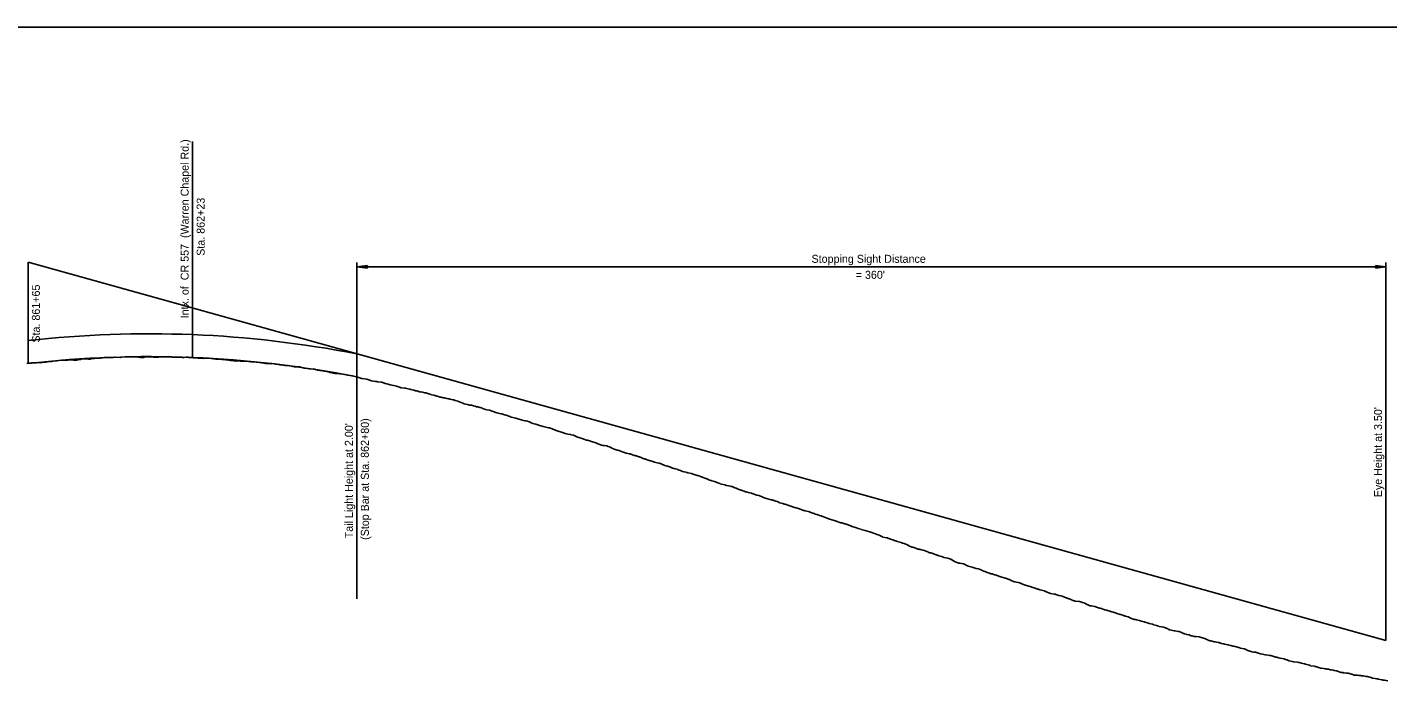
# Model space of a CAD drawing. Extents: x -1395 to 1843, y -1176 to 1887.
# Drawn here: x 1124.1 to 1600, y 762.7 to 991.4 of the extents above; entities that cross this region are included whole.
import ezdxf

# ---------------------------------------------------------------- set-up
doc = ezdxf.new("R2010")
doc.units = 0
doc.layers.add('SV_X_Toe_of_Slope', color=7, linetype='Continuous')
doc.layers.add('UT_X_Telecom', color=7, linetype='Continuous')

msp = doc.modelspace()

# ---------------------------------------------------------------- linework, layer by layer
at = {"layer": 'SV_X_Toe_of_Slope'}
for p, q in [((1059.41, 991.44), (1659.41, 991.44)), ((1181.98, 875.86), (1181.98, 951.44)), ((1124.41, 873.75), (1124.41, 909.2)), ((1124.41, 909.2), (1599.41, 776.77)), ((1239.41, 791.44), (1239.41, 909.13)), ((1599.41, 776.77), (1599.41, 909.13)), ((1239.41, 907.59), (1243.12, 908.08)), ((1239.41, 907.59), (1599.41, 907.59)), ((1243.11, 907.09), (1239.41, 907.59)), ((1243.11, 907.09), (1243.11, 907.09)), ((1243.12, 908.08), (1243.12, 908.08)), ((1599.41, 907.59), (1595.7, 907.09)), ((1595.7, 907.09), (1595.71, 907.09)), ((1595.72, 908.08), (1595.72, 908.08)), ((1595.72, 908.08), (1599.41, 907.59))]:
    msp.add_line(p, q, dxfattribs=at)
for centre, major_axis, ratio, start_param, end_param in [((1244.06, 907.58), (-1.13, 0), 0.8, 5.69288, 6.856679), ((1594.77, 907.6), (1.13, 0), 0.8, 5.69288, 6.856679), ((1166.87, -5112.73), (0, 5996.89), 0.25, 6.234777, 6.311506), ((1166.87, -5112.73), (0, 5988.89), 0.25, 6.234712, 6.311544)]:
    msp.add_ellipse(centre, major_axis=major_axis, ratio=ratio, start_param=start_param, end_param=end_param, dxfattribs=at)
at = {"layer": 'UT_X_Telecom'}
msp.add_lwpolyline([(1123.99, 873.76), (1125.65, 874.04), (1125.77, 874.04), (1127.25, 874.02), (1127.58, 874.08), (1128.53, 874.04), (1128.88, 874.05), (1129.16, 874.12), (1129.39, 874.16), (1130.64, 874.24), (1130.65, 874.24), (1130.66, 874.24), (1131.16, 874.36), (1132.5, 874.44), (1132.56, 874.44), (1132.64, 874.47), (1132.9, 874.57), (1133.13, 874.59), (1134.05, 874.66), (1134.46, 874.68), (1134.52, 874.71), (1135.02, 874.8), (1136.15, 874.87), (1136.2, 874.87), (1136.46, 874.94), (1137.1, 874.94), (1137.85, 874.93), (1137.9, 874.92), (1137.98, 874.94), (1138.36, 874.98), (1139.32, 875.02), (1139.54, 875.03), (1139.62, 875.03), (1140.2, 874.99), (1140.47, 874.97), (1141.15, 874.92), (1141.49, 874.98), (1142.4, 875.19), (1142.72, 875.21), (1142.93, 875.26), (1144.02, 875.44), (1144.18, 875.43), (1144.42, 875.37), (1145.51, 875.27), (1145.89, 875.25), (1146.07, 875.24), (1146.39, 875.35), (1147.52, 875.54), (1147.91, 875.58), (1149.1, 875.6), (1149.19, 875.6), (1149.57, 875.57), (1149.59, 875.58), (1150.49, 875.73), (1151.02, 875.83), (1151.21, 875.81), (1151.26, 875.8), (1151.27, 875.8), (1151.31, 875.8), (1152.9, 875.84), (1152.93, 875.84), (1153.68, 875.87), (1154.12, 875.88), (1154.69, 875.92), (1154.85, 875.92), (1156.61, 875.91), (1156.93, 875.99), (1158.2, 876.05), (1158.38, 876.04), (1158.49, 876.05), (1159.8, 876.08), (1160.01, 876.07), (1160.37, 876.1), (1160.46, 876.12), (1161.53, 876.08), (1161.55, 876.08), (1161.96, 876.12), (1162.01, 876.12), (1162.05, 876.11), (1163.08, 875.95), (1163.58, 875.9), (1163.75, 875.91), (1164.62, 875.9), (1164.76, 875.9), (1165.1, 875.99), (1165.39, 876.06), (1166.64, 876.11), (1166.68, 876.12), (1166.91, 876.09), (1168.25, 875.95), (1168.33, 875.93), (1168.42, 875.93), (1168.91, 875.95), (1169.49, 875.98), (1170.01, 876.02), (1170.79, 876.04), (1171.78, 876.07), (1172.24, 876.11), (1172.74, 876.14), (1173.4, 876.16), (1173.58, 876.14), (1174.13, 876.05), (1174.66, 876), (1175.25, 875.94), (1175.41, 875.92), (1176.44, 875.99), (1176.57, 876), (1176.6, 876), (1177.13, 876), (1178.34, 875.89), (1178.4, 875.89), (1178.45, 875.88), (1178.5, 875.89), (1178.9, 875.89), (1179.66, 875.94), (1180.29, 875.95), (1180.64, 875.88), (1181.26, 875.84), (1182.1, 875.79), (1182.38, 875.76), (1183.3, 875.71), (1183.92, 875.66), (1184.12, 875.63), (1184.94, 875.61), (1185.44, 875.58), (1185.75, 875.56), (1185.82, 875.57), (1187.45, 875.6), (1187.49, 875.6), (1187.5, 875.6), (1187.51, 875.6), (1187.62, 875.59), (1189.25, 875.42), (1190.09, 875.32), (1190.85, 875.24), (1190.94, 875.24), (1191.05, 875.23), (1192.23, 875.14), (1192.39, 875.12), (1192.65, 875.11), (1193.52, 875.04), (1193.86, 875), (1194.48, 874.98), (1194.78, 874.91), (1195.18, 874.83), (1195.4, 874.78), (1196.4, 874.71), (1196.75, 874.69), (1196.95, 874.62), (1197.93, 874.65), (1198.38, 874.66), (1198.7, 874.62), (1200.37, 874.61), (1200.48, 874.61), (1200.62, 874.6), (1200.65, 874.59), (1202.33, 874.31), (1202.51, 874.29), (1202.61, 874.29), (1202.66, 874.29), (1203.69, 874.3), (1204.17, 874.26), (1204.31, 874.24), (1204.51, 874.22), (1205.34, 874.11), (1205.94, 874.05), (1206.04, 874.03), (1206.22, 873.99), (1207.49, 873.8), (1207.73, 873.76), (1207.84, 873.77), (1208.79, 873.74), (1209.35, 873.68), (1209.67, 873.7), (1210.47, 873.63), (1210.94, 873.56), (1211.25, 873.54), (1211.58, 873.48), (1212.53, 873.34), (1212.6, 873.33), (1212.75, 873.3), (1213.5, 873.2), (1214.1, 873.12), (1214.29, 873.1), (1215.03, 873.07), (1215.36, 873.06), (1215.8, 872.97), (1216.01, 872.91), (1216.61, 872.81), (1217.52, 872.57), (1217.81, 872.56), (1219.35, 872.54), (1220.98, 872.16), (1221.01, 872.16), (1221.01, 872.16), (1221.19, 872.12), (1222.09, 871.97), (1222.84, 871.84), (1222.88, 871.84), (1222.97, 871.84), (1224.59, 871.8), (1224.66, 871.79), (1224.92, 871.7), (1225.79, 871.44), (1225.87, 871.41), (1226.06, 871.37), (1226.56, 871.27), (1227.35, 871.24), (1227.65, 871.24), (1227.8, 871.21), (1228.14, 871.13), (1229.34, 870.83), (1229.48, 870.81), (1230.12, 870.65), (1231.11, 870.34), (1231.28, 870.35), (1231.66, 870.3), (1232.54, 870.28), (1232.8, 870.27), (1233.42, 870.15), (1233.85, 870.11), (1233.97, 870.09), (1234.56, 870), (1235.15, 869.93), (1235.94, 869.79), (1236.27, 869.72), (1237.18, 869.56), (1237.86, 869.42), (1238.31, 869.32), (1239.34, 869.1), (1239.52, 869.03), (1239.65, 869.01), (1240.08, 868.84), (1241.03, 868.54), (1241.17, 868.52), (1241.33, 868.5), (1242.77, 868.3), (1242.88, 868.29), (1242.92, 868.28), (1243.6, 868.04), (1244.54, 867.71), (1245.98, 867.47), (1246.4, 867.41), (1246.46, 867.41), (1246.6, 867.39), (1248.08, 867.25), (1248.39, 867.15), (1248.47, 867.12), (1249.35, 866.8), (1249.88, 866.64), (1249.94, 866.61), (1250.67, 866.39), (1251.05, 866.32), (1251.65, 866.2), (1252.28, 866.07), (1252.85, 865.94), (1253.28, 865.8), (1254.63, 865.33), (1254.73, 865.29), (1254.76, 865.29), (1254.89, 865.33), (1255.04, 865.29), (1256.22, 865.17), (1256.55, 865.1), (1256.65, 865.08), (1256.75, 865.05), (1257.96, 864.75), (1258.3, 864.67), (1259.28, 864.44), (1259.49, 864.39), (1259.97, 864.24), (1260.39, 864.14), (1261.29, 863.88), (1261.68, 863.81), (1262.39, 863.68), (1263.15, 863.54), (1263.37, 863.47), (1263.55, 863.44), (1263.85, 863.36), (1264.94, 863.06), (1265.43, 862.89), (1265.56, 862.84), (1266.34, 862.64), (1266.71, 862.53), (1267.43, 862.35), (1267.68, 862.29), (1268.17, 862.11), (1268.35, 862.04), (1268.42, 862.03), (1268.94, 861.93), (1269.63, 861.79), (1269.66, 861.78), (1270.02, 861.69), (1270.93, 861.51), (1271.44, 861.38), (1271.5, 861.37), (1271.72, 861.34), (1272.11, 861.25), (1272.94, 861.09), (1273.02, 861.07), (1273.3, 861.03), (1273.77, 860.84), (1274.7, 860.58), (1274.74, 860.57), (1275.02, 860.46), (1275.31, 860.36), (1276.53, 859.88), (1276.69, 859.81), (1277.01, 859.68), (1278.11, 859.44), (1278.48, 859.35), (1278.58, 859.32), (1278.88, 859.22), (1279.47, 859.12), (1280.25, 858.93), (1280.75, 858.79), (1281.27, 858.65), (1281.77, 858.54), (1282.46, 858.34), (1282.55, 858.31), (1282.85, 858.22), (1283.34, 858.07), (1283.37, 858.06), (1284.15, 857.73), (1284.34, 857.65), (1284.37, 857.64), (1284.92, 857.5), (1285.83, 857.39), (1286.21, 857.26), (1286.45, 857.23), (1286.78, 857.11), (1287.06, 857), (1288.07, 856.6), (1288.34, 856.54), (1288.86, 856.42), (1289.78, 856.15), (1289.95, 856.12), (1290.09, 856.1), (1291.06, 855.82), (1291.68, 855.68), (1291.68, 855.68), (1292.91, 855.21), (1293.16, 855.12), (1293.17, 855.11), (1293.34, 855.03), (1293.49, 854.96), (1294.93, 854.68), (1294.94, 854.68), (1295.04, 854.65), (1295.4, 854.55), (1295.42, 854.54), (1296.56, 854.16), (1296.87, 854.09), (1297.14, 854.02), (1297.29, 853.98), (1298.2, 853.71), (1298.54, 853.64), (1299.07, 853.52), (1299.65, 853.33), (1299.86, 853.3), (1300.37, 853.04), (1300.95, 852.8), (1301.49, 852.65), (1302, 852.51), (1302.72, 852.27), (1303.01, 852.17), (1303.28, 852.1), (1303.46, 852.05), (1304.55, 851.71), (1305.02, 851.6), (1305.04, 851.6), (1305.05, 851.6), (1306.4, 851.29), (1306.59, 851.25), (1306.79, 851.21), (1307.11, 851.09), (1307.78, 850.84), (1308.51, 850.54), (1309.49, 850.17), (1310.16, 850), (1310.95, 849.74), (1311.7, 849.52), (1311.91, 849.43), (1312.25, 849.27), (1313.17, 849.03), (1313.25, 849.01), (1314.01, 848.94), (1314.22, 848.91), (1314.43, 848.85), (1315.04, 848.69), (1315.05, 848.68), (1315.14, 848.64), (1316.11, 848.16), (1316.62, 847.97), (1316.76, 847.93), (1317.42, 847.77), (1317.93, 847.58), (1318.43, 847.44), (1318.46, 847.43), (1318.49, 847.42), (1319.73, 846.97), (1320.07, 846.96), (1320.09, 846.95), (1320.11, 846.95), (1321.51, 846.52), (1321.55, 846.51), (1323, 845.98), (1323.28, 845.87), (1323.35, 845.83), (1323.39, 845.82), (1323.5, 845.77), (1324.96, 845.18), (1325.12, 845.15), (1325.16, 845.14), (1325.5, 845.11), (1325.88, 845.05), (1326.71, 844.93), (1326.8, 844.91), (1327.36, 844.71), (1327.8, 844.56), (1328.3, 844.36), (1328.54, 844.2), (1328.61, 844.16), (1329.14, 843.94), (1329.8, 843.67), (1329.81, 843.67), (1330.53, 843.47), (1330.72, 843.41), (1331.46, 843.19), (1332.02, 842.97), (1332.56, 842.75), (1333.03, 842.6), (1333.24, 842.55), (1333.6, 842.43), (1334.76, 842.14), (1335, 842.1), (1335.79, 841.8), (1336.37, 841.6), (1336.4, 841.59), (1336.72, 841.55), (1337.01, 841.45), (1337.18, 841.4), (1338.1, 841.14), (1338.27, 841.08), (1339.06, 840.75), (1339.26, 840.68), (1339.79, 840.45), (1340.02, 840.37), (1340.11, 840.35), (1340.94, 840), (1341.66, 839.81), (1341.81, 839.78), (1342.1, 839.71), (1342.63, 839.55), (1343.54, 839.27), (1344.47, 839.01), (1345.1, 838.89), (1345.22, 838.85), (1345.83, 838.6), (1346.55, 838.31), (1346.65, 838.25), (1347.14, 838.02), (1348.01, 837.82), (1348.16, 837.78), (1348.47, 837.71), (1348.93, 837.58), (1349.65, 837.25), (1349.79, 837.18), (1349.93, 837.14), (1350.8, 836.94), (1351.41, 836.77), (1351.62, 836.7), (1352.18, 836.43), (1352.64, 836.29), (1353.12, 836.06), (1353.32, 835.98), (1353.46, 835.93), (1354.92, 835.6), (1354.96, 835.59), (1355.14, 835.55), (1356.48, 835.24), (1356.67, 835.16), (1357.46, 834.9), (1358.5, 834.55), (1358.59, 834.53), (1358.61, 834.52), (1358.64, 834.51), (1359.93, 834.06), (1360.24, 833.95), (1360.4, 833.93), (1360.56, 833.89), (1361.18, 833.68), (1361.88, 833.42), (1361.9, 833.41), (1362.26, 833.18), (1362.76, 832.99), (1363.34, 832.81), (1363.54, 832.73), (1364.49, 832.44), (1364.86, 832.33), (1365.09, 832.21), (1365.7, 831.96), (1366.44, 831.71), (1366.53, 831.68), (1366.94, 831.59), (1368.19, 831.29), (1368.3, 831.26), (1368.36, 831.23), (1368.75, 831.07), (1370.15, 830.78), (1370.23, 830.77), (1370.29, 830.76), (1370.66, 830.66), (1371.6, 830.29), (1372.07, 830.15), (1372.36, 830.01), (1372.57, 829.91), (1373.4, 829.56), (1373.75, 829.46), (1373.91, 829.39), (1374.42, 829.23), (1374.86, 829.07), (1375.38, 828.89), (1375.58, 828.82), (1376.4, 828.66), (1376.83, 828.53), (1376.98, 828.5), (1377.43, 828.34), (1377.67, 828.27), (1378.44, 828), (1378.67, 827.93), (1379.38, 827.73), (1380.11, 827.52), (1380.32, 827.48), (1380.96, 827.2), (1381.69, 826.89), (1382.04, 826.74), (1382.3, 826.65), (1382.68, 826.53), (1383.57, 826.25), (1384.34, 826.08), (1384.71, 826.01), (1385.15, 825.87), (1385.4, 825.78), (1385.53, 825.76), (1385.66, 825.7), (1386.84, 825.31), (1387.16, 825.12), (1387.41, 825.01), (1388.4, 824.72), (1388.65, 824.65), (1388.89, 824.59), (1389.24, 824.5), (1390.5, 824.03), (1390.53, 824.02), (1390.89, 823.92), (1390.89, 823.92), (1390.89, 823.92), (1392.49, 823.42), (1392.6, 823.39), (1393.9, 823.03), (1394.04, 822.97), (1394.11, 822.94), (1394.24, 822.89), (1395.7, 822.34), (1395.83, 822.29), (1396.18, 822.22), (1397.29, 822.02), (1397.78, 821.88), (1398.23, 821.67), (1398.86, 821.41), (1399.34, 821.21), (1399.77, 821.05), (1400.25, 820.92), (1400.39, 820.88), (1401.22, 820.62), (1401.85, 820.46), (1402.07, 820.39), (1402.46, 820.25), (1403.55, 819.76), (1403.88, 819.67), (1404.8, 819.26), (1405.31, 819.12), (1405.43, 819.09), (1405.58, 819.04), (1406.86, 818.65), (1406.88, 818.65), (1406.99, 818.61), (1407.08, 818.59), (1407.4, 818.5), (1408, 818.29), (1408.72, 818.04), (1409.12, 817.95), (1410.09, 817.67), (1410.5, 817.54), (1410.67, 817.49), (1410.92, 817.42), (1412.4, 816.79), (1412.49, 816.76), (1412.51, 816.74), (1412.57, 816.72), (1412.62, 816.71), (1414.25, 816.23), (1414.73, 816.07), (1415.67, 815.75), (1415.87, 815.66), (1416.81, 815.43), (1417.24, 815.33), (1417.56, 815.22), (1418.43, 815.01), (1418.83, 814.88), (1419.22, 814.73), (1419.51, 814.58), (1420.15, 814.36), (1420.48, 814.25), (1420.84, 814.14), (1421.44, 813.9), (1421.82, 813.75), (1422.11, 813.64), (1423.33, 813.05), (1423.38, 813.03), (1423.46, 813.01), (1424.89, 812.74), (1425.11, 812.7), (1425.2, 812.64), (1425.49, 812.53), (1426.39, 812.13), (1426.87, 812.01), (1427.42, 811.84), (1427.43, 811.84), (1427.44, 811.83), (1428.18, 811.59), (1428.62, 811.44), (1428.74, 811.41), (1429.34, 811.27), (1429.77, 811.15), (1430.27, 810.93), (1430.9, 810.73), (1431.08, 810.65), (1431.98, 810.29), (1432.07, 810.25), (1432.15, 810.22), (1432.79, 809.87), (1433.7, 809.46), (1433.88, 809.44), (1434.29, 809.32), (1434.55, 809.26), (1435.16, 809.02), (1435.64, 808.83), (1436.11, 808.73), (1436.33, 808.68), (1436.59, 808.62), (1437.35, 808.48), (1437.95, 808.29), (1438.22, 808.22), (1438.81, 807.94), (1439.17, 807.8), (1439.47, 807.67), (1439.81, 807.54), (1440.15, 807.46), (1440.93, 807.22), (1441.13, 807.17), (1442.39, 806.74), (1442.49, 806.69), (1442.57, 806.66), (1442.96, 806.49), (1443.95, 806.21), (1444.04, 806.19), (1444.78, 805.91), (1444.89, 805.86), (1446.01, 805.65), (1446.07, 805.64), (1446.1, 805.63), (1446.8, 805.42), (1446.93, 805.35), (1448.12, 804.67), (1448.65, 804.36), (1448.65, 804.36), (1448.65, 804.36), (1449.94, 803.94), (1450.03, 803.91), (1450.24, 803.89), (1450.93, 803.76), (1451.53, 803.65), (1451.63, 803.62), (1451.66, 803.6), (1451.94, 803.48), (1452.28, 803.32), (1453.06, 802.97), (1453.25, 802.88), (1454.14, 802.61), (1454.6, 802.46), (1455.03, 802.34), (1455.69, 802.16), (1456.09, 802.05), (1456.76, 801.89), (1456.86, 801.87), (1457.41, 801.68), (1457.76, 801.56), (1458.18, 801.36), (1458.76, 801.11), (1459.03, 801.02), (1459.4, 800.91), (1459.95, 800.67), (1460.67, 800.38), (1460.77, 800.37), (1461.15, 800.21), (1461.69, 800.11), (1462.44, 799.83), (1462.98, 799.7), (1463.12, 799.66), (1463.36, 799.56), (1464.21, 799.27), (1464.33, 799.23), (1465.08, 798.98), (1465.9, 798.73), (1465.93, 798.72), (1465.94, 798.72), (1466.98, 798.44), (1467.48, 798.21), (1467.58, 798.16), (1467.68, 798.12), (1468.55, 797.68), (1469.17, 797.5), (1469.28, 797.45), (1469.53, 797.4), (1470.03, 797.28), (1470.81, 797.12), (1470.84, 797.12), (1470.84, 797.12), (1471.53, 796.88), (1472.25, 796.59), (1472.61, 796.47), (1473.22, 796.22), (1473.23, 796.22), (1473.35, 796.18), (1473.67, 796.08), (1474.14, 795.94), (1474.47, 795.83), (1474.5, 795.82), (1474.94, 795.68), (1475.85, 795.39), (1476.39, 795.21), (1476.64, 795.16), (1477.56, 794.84), (1477.82, 794.74), (1478.31, 794.55), (1478.38, 794.53), (1479.92, 794.2), (1479.98, 794.19), (1480, 794.19), (1480.1, 794.14), (1481.69, 793.34), (1482, 793.26), (1483.38, 793.05), (1483.67, 793.02), (1483.73, 793.01), (1483.89, 792.97), (1485.01, 792.6), (1485.62, 792.46), (1485.71, 792.42), (1486.52, 792.18), (1486.72, 792.12), (1487.53, 791.78), (1487.55, 791.77), (1487.62, 791.75), (1488.49, 791.45), (1488.55, 791.43), (1489.17, 791.2), (1490.23, 790.74), (1490.34, 790.7), (1490.35, 790.7), (1490.45, 790.66), (1490.65, 790.61), (1492.14, 790.43), (1492.19, 790.43), (1492.21, 790.42), (1493.27, 790.11), (1493.75, 789.97), (1493.89, 789.93), (1493.91, 789.92), (1494.03, 789.88), (1494.39, 789.7), (1495.38, 789.22), (1495.58, 789.13), (1495.61, 789.12), (1495.9, 789.01), (1495.94, 789), (1495.95, 789), (1496.42, 788.92), (1497.41, 788.75), (1497.57, 788.69), (1498.5, 788.38), (1499.21, 788.18), (1499.43, 788.12), (1499.86, 787.97), (1500.96, 787.58), (1501.22, 787.55), (1501.63, 787.46), (1502.8, 787.05), (1503.13, 786.93), (1504.32, 786.62), (1504.47, 786.57), (1504.63, 786.53), (1504.9, 786.46), (1505.27, 786.31), (1506.09, 785.99), (1506.37, 785.93), (1506.58, 785.9), (1507.35, 785.64), (1507.8, 785.51), (1507.89, 785.5), (1508.33, 785.36), (1509.28, 785.05), (1509.48, 784.97), (1509.69, 784.86), (1510.06, 784.66), (1511.1, 784.25), (1511.26, 784.2), (1511.38, 784.2), (1511.76, 784.14), (1512.13, 784.04), (1513.05, 783.85), (1513.24, 783.78), (1513.43, 783.69), (1513.87, 783.56), (1514.78, 783.31), (1515.05, 783.23), (1515.53, 783.11), (1516.39, 782.88), (1516.58, 782.83), (1517.78, 782.49), (1517.92, 782.45), (1518.06, 782.41), (1518.23, 782.35), (1519.17, 782.04), (1519.51, 781.92), (1519.9, 781.79), (1520.12, 781.75), (1521.68, 781.47), (1523.1, 780.85), (1523.39, 780.73), (1523.61, 780.62), (1523.78, 780.56), (1525.29, 780.24), (1525.42, 780.21), (1525.72, 780.18), (1526.71, 780.02), (1526.98, 779.96), (1527.1, 779.96), (1527.67, 779.8), (1528.55, 779.33), (1528.67, 779.29), (1528.92, 779.2), (1529.55, 779), (1529.67, 778.98), (1530.52, 778.81), (1531.04, 778.6), (1531.3, 778.49), (1531.44, 778.45), (1532.35, 778.22), (1532.8, 778.2), (1532.86, 778.19), (1534.13, 778.07), (1534.18, 778.05), (1534.37, 778.05), (1535.56, 777.65), (1535.96, 777.5), (1536.03, 777.47), (1536.73, 777.17), (1537.77, 776.74), (1538.14, 776.66), (1539.38, 776.41), (1539.58, 776.38), (1540.7, 776.14), (1540.92, 776.1), (1541.22, 776.03), (1541.25, 776.02), (1541.92, 775.83), (1542.4, 775.69), (1542.54, 775.66), (1542.92, 775.57), (1543.55, 775.42), (1544.05, 775.32), (1544.29, 775.28), (1544.46, 775.21), (1545.13, 775.05), (1545.86, 774.88), (1546.13, 774.8), (1546.69, 774.68), (1547.77, 774.35), (1547.9, 774.32), (1548.57, 774.19), (1549.78, 773.93), (1549.82, 773.93), (1549.87, 773.92), (1551.13, 773.35), (1551.77, 773.07), (1551.89, 773.05), (1552.47, 772.91), (1553.2, 772.79), (1553.52, 772.74), (1553.68, 772.71), (1553.72, 772.7), (1554.44, 772.48), (1555.55, 772.16), (1556.18, 772.03), (1557.13, 771.83), (1557.29, 771.77), (1558.24, 771.65), (1558.72, 771.62), (1559.04, 771.57), (1559.15, 771.53), (1559.8, 771.29), (1560.18, 771.21), (1560.52, 771.12), (1560.8, 771.04), (1561.28, 770.94), (1561.86, 770.79), (1562.23, 770.69), (1562.26, 770.68), (1562.36, 770.66), (1563.63, 770.41), (1563.8, 770.36), (1563.83, 770.36), (1563.99, 770.31), (1564.22, 770.21), (1564.67, 770.03), (1565.5, 769.71), (1566.64, 769.51), (1567.03, 769.4), (1567.14, 769.38), (1567.22, 769.39), (1568.46, 769.22), (1568.87, 769.11), (1569.02, 769.08), (1569.9, 768.89), (1570.82, 768.63), (1570.9, 768.62), (1571.3, 768.51), (1572.61, 768.18), (1572.93, 768.03), (1573.05, 767.99), (1574.36, 767.8), (1574.46, 767.78), (1574.75, 767.71), (1575.78, 767.4), (1575.95, 767.35), (1576.57, 767.13), (1576.6, 767.13), (1576.69, 767.11), (1577.63, 767.02), (1578.09, 766.91), (1578.44, 766.86), (1578.85, 766.8), (1579.25, 766.75), (1580.03, 766.61), (1580.19, 766.58), (1580.38, 766.54), (1581.02, 766.44), (1581.28, 766.38), (1582.06, 766.2), (1582.45, 766.11), (1582.81, 765.97), (1583.06, 765.89), (1583.72, 765.62), (1584.3, 765.59), (1584.6, 765.55), (1584.76, 765.52), (1585.61, 765.45), (1586.28, 765.34), (1586.42, 765.31), (1586.61, 765.24), (1587.38, 765.01), (1587.42, 764.99), (1588.09, 764.77), (1588.18, 764.75), (1588.72, 764.69), (1589.06, 764.66), (1589.48, 764.64), (1589.89, 764.62), (1590.48, 764.54), (1590.79, 764.51), (1590.99, 764.48), (1591.38, 764.43), (1591.89, 764.33), (1592.39, 764.23), (1592.87, 764.17), (1592.98, 764.17), (1594.08, 763.9), (1594.25, 763.85), (1594.7, 763.68), (1595.62, 763.51), (1596.14, 763.4), (1596.44, 763.39), (1596.83, 763.31), (1598.01, 763.08), (1598.18, 763.01), (1598.32, 762.98), (1598.91, 762.89), (1600.07, 762.72)], dxfattribs=at)

# ---------------------------------------------------------------- texts
at = {"layer": 'SV_X_Toe_of_Slope'}
for s, rotation, p in [('Intx. of  CR 557  (Warren Chapel Rd.)', 90, (1180.58, 889.58)), ('Sta. 862+23', 90, (1186.18, 911.45)), ('Stopping Sight Distance', 360, (1398.47, 908.99)), ("= 360'", 360, (1413.93, 903.39)), ('Sta. 861+65', 90, (1128.55, 881.07)), ("Eye Height at 3.50'", 90, (1598.01, 826.96)), ("Tail Light Height at 2.00'", 90, (1238.01, 812.6)), ('(Stop Bar at Sta. 862+80)', 90, (1243.61, 812.03))]:
    msp.add_text(s, height=2.8, rotation=rotation, dxfattribs=at).set_placement(p)

doc.saveas('drawing.dxf')
